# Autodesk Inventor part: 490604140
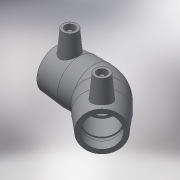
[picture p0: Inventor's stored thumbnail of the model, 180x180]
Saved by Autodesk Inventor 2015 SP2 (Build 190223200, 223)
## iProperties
Created: 2017-06
Part Number: 490604140
Material: Generic
Description: PLASSON 45° ELBOW 140
Document SubType Name: Modeling
Designer: KIM
Mass: 55.0731 g
Surface Area: 148.067 cm^2
Volume: 55.0731 cm^3
Density: 1 g/cm^3
Appearance: Default
Author: KIM
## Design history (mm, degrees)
derived "490604.ipt"
feature "Solid1::490604.ipt"
tag "TaggingFeature1"
body "Solid1"
other parameters: "d2" = 182, "d4" = 85.5, "d5" = 163.8, "d8" = 168 deg, "d10" = 36.8, "d11" = 12.26667, "d14" = 17.6296, "d19" = 3.52592, "d20" = 168 deg, "d22" = 167.44, "d23" = 182, "d24" = 162.4168, "d29" = 95, "d30" = 15, "d31" = 119.7, "d34" = 5 deg, "d35" = 12, "d39" = 0, "d41" = 4, "d42" = 14, "d43" = 0, "d44" = 9.6, "d45" = 4.8, "d46" = 6, "d47" = 0, "d50" = 119, "d51" = 36.8, "d52" = 92, "d54" = 135 deg, "d67" = 45 deg, "d71" = 135 deg, "d75" = 9.1, "d82" = 45 deg, "d83" = 92, "d84" = 163.8, "d86" = 81.9, "d87" = 135 deg, "d88" = 342, "d90" = 92, "d91" = 0, "d92" = 92, "d93" = 0, "d94" = 135 deg, "d95" = 83.72, "d98" = 342, "d99" = 109.44, "d101" = 3, "d102" = 0, "d103" = 3, "d104" = 0, "d105" = 26.68, "d106" = 6.67, "L_" = 342, "L_1" = 92, "D_" = 182, "A_" = 95, "d_2" = 12
